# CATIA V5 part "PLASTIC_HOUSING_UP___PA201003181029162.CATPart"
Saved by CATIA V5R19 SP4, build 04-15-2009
Part number: PLASTIC_HOUSING_UP___PA201003181029162
Bounding box of the stored display mesh (mm): x -26 to 26, y -20.64 to 95, z -0.5 to 11
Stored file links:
  E:\CadInnWork\1\PLASTIC_HOUSING_UP___PA201003181029162.CATPart
  C:\Documents and Settings\moren\Bureau\3D models\Lampe\CATIA_V5\pocket_lamp.CATProduct
  C:\Documents and Settings\moren\Bureau\3D models\Lampe\CATIA_V5\switch.CATPart
  C:\Documents and Settings\moren\Bureau\3D models\Lampe\CATIA_V5\led.CATPart
  C:\Documents and Settings\moren\Bureau\3D models\Lampe\CATIA_V5\insert.CATPart
  C:\Documents and Settings\moren\Bureau\3D models\Lampe\CATIA_V5\battery_holder.CATPart
  C:\Documents and Settings\moren\Bureau\3D models\Lampe\CATIA_V5\printed_circuit_board.CATPart
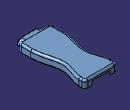
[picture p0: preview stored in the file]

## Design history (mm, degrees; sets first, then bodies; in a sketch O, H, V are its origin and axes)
Parameters
  Update = false
  PDM_version = "A"
  PDM_iteration = 1
  PDM_owner = "moren                    "
  PDM_comment = ""
  PDM_partnumber = "PA002170EA6A57201003181029160002"
Set1
  DatumCurve1: linked copy from another document
  Plane1: linked copy from another document
  DatumCurve2: linked copy from another document
  DatumCurve3: linked copy from another document
  DatumSurface1: linked copy from another document
  Plane2: linked copy from another document
  DatumCurve4: linked copy from another document
  DatumCurve5: linked copy from another document
  DatumSurface2: linked copy from another document
  DatumCurve6: linked copy from another document
  DatumCurve7: linked copy from another document
Body1 (main body)
  Sketch1 on xy-plane, origin (0, 0, 0), H (1, 0, 0), V (0, 1, 0)
    point P1 (0, -10.14)
    line L1 (0, -10.14) -> (-21, -10.14)
    point P2 (-24, -10.14)
    line L2 (0, 93) -> (-21, 93)
    line L3 (-24, 90) -> (-24, 85.2347)
    point P4 (-24, -10.14)
    reference projected line E1 (-14.9, -10.14) -> (-9.5, -10.14) from edge of DatumCurve2
    reference projected circle E2 centre (-20, 89) radius 2.5 from edge of DatumCurve3
    arc A1 centre (-21, 90) radius 3 from (-21, 93) to (-24, 90) ccw
    arc A2 centre (-21, -7.14) radius 3 from (-21, -10.14) to (-24, -7.14) cw
    line L4 (0, 93) -> (0, -10.14)
    spline S1 through (-24, 8.6583) (-20.9977, 71.7619) (-24, 85.2347)
    reference intersected line E3 through (0, 0) direction (0, 1) from Plane2
    line L5 (-24, 8.6583) -> (-24, -7.14)
    point P11 (-24, 85.2347)
    point P12 (-24, 8.6583)
    reference projected line E4 (-13.2, 95) -> (13.2, 95) from DatumCurve1
    point P13 (-24, 8.6583)
    point P14 (-24, 85.2347)
    distance E2 L3 = 1.5
    radius A1 = 3
    radius A2 = 3
    distance S1 E3 = 16.5
    distance L2 E4 = 2
    coincidence: P1 V, P4 P2, L1 E1, L1 P2, L3 P4, P13 L3, P14 L3, P14 P11, P13 P12, L3 L5
    horizontal: L1 H, L2 H
    vertical: L3 V, L4 V, L5 V
    tangency: A1 L2, A1 L3, A2 L1, A2 L3
  Pad1: profile Sketch1, direction (0, 0, 1), up to face of DatumSurface1
  Thickness1: Thickness 1, Face end face of Pad1
  Fillet1: radius 1, on edge [end face of Pad1 | face of Pad1 from Sketch1.S1]
  Shell1: IntOffset 0, Face (start face of Pad1; face of Pad1 from Sketch1.L4), ExtOffset 2
  Sketch2 on end face of Pad1, origin (0, 0, 9), H (1, 0, 0), V (0, -1, 0)
    circle A1 centre (-20, 6.14) radius 4.5
    circle A2 centre (-20, 6.14) radius 2.4
    radius A2 = 2.4
    distance A2 A1 = 2.1
  Pad2: profile Sketch2, direction (0, 0, -1), length 6.5
  Fillet2: radius 0.5, on edge [end face of Pad1 | face of Pad2 from Sketch2.A1]; edge [face of Pad1 from Sketch1.A2 | end face of Pad2]; edge [face of Pad2 from Sketch2.A1 | end face of Pad2]
  Sketch3 on end face of Pad1, origin (0, 0, 9), H (1, 0, 0), V (0, -1, 0)
    circle A1 centre (-20, -89) radius 2.4
    reference projected circle E1 centre (-20, -89) radius 2.5 from edge of DatumCurve3
    circle A2 centre (-20, -89) radius 4.5
    radius A1 = 2.4
    distance A1 A2 = 2.1
    concentricity: A1 E1
  Pad3: profile Sketch3, direction (0, 0, -1), length 6.5
  Fillet3: radius 0.5, on edge [end face of Pad1 | face of Pad3 from Sketch3.A2]; edge [face of Pad1 from Sketch1.A1 | end face of Pad3]; edge [face of Pad3 from Sketch3.A2 | end face of Pad3]
  Sketch4 on end face of Pad1, origin (0, 0, 9), H (1, 0, 0), V (0, -1, 0)
    point P1 (0, 0.2)
    line L1 (0, 0.2) -> (-16, 0.2)
    line L2 (-16, 0.2) -> (-16, -1.2)
    line L3 (-16, -1.2) -> (0, -1.2)
    point P4 (0, -1.2)
    reference projected line E1 (15, -1) -> (-15, -1) from edge of DatumCurve5
    reference intersected line E2 through (0, 0) direction (-1, 0) from face of DatumSurface2
    reference projected line E3 (-15, 0) -> (-15, -1) from edge of DatumCurve6
    line L4 (0, -1.2) -> (0, -2.95)
    line L5 (0, -2.95) -> (-15.8, -2.95)
    line L6 (-17.75, -27.95) -> (-17.75, -0.05)
    line L7 (-15.75, 1.95) -> (0, 1.95)
    point P6 (0, 1.95)
    line L8 (0, 1.95) -> (0, 0.2)
    arc A1 centre (-15.75, -0.05) radius 2 from (-15.75, 1.95) to (-17.75, -0.05) ccw
    point P10 (-17.75, -27.95)
    line L9 (-16, -3.15) -> (-16, -27.95)
    line L10 (-16, -27.95) -> (-17.75, -27.95)
    point P12 (-17.75, -27.95)
    arc A2 centre (-15.8, -3.15) radius 0.2 from (-15.8, -2.95) to (-16, -3.15) ccw
    distance E1 L3 = 0.2
    distance L1 E2 = 0.2
    distance E3 L2 = 1
    distance L1 L7 = 1.75
    distance L2 L6 = 1.75
    distance L5 L3 = 1.75
    radius A1 = 2
    distance L9 L6 = 1.75
    radius A2 = 0.2
    distance L10 L5 = 25
    coincidence: P1 V, P4 V, P6 V, P12 L6, P10 P12
    horizontal: L1 H, L3 H, L5 H, L7 H, L10 H
    vertical: L2 V, L4 V, L6 V, L8 V, L9 V
    tangency: A1 L7, A1 L6, A2 L5, A2 L9
  Pad4: profile Sketch4, direction (0, 0, -1), length 7.5
  Fillet4: radius 0.5, on edge [face of Pad4 from Sketch4.L5 | end face of Pad1]; edge [face of Pad4 from Sketch4.L6 | end face of Pad1]; edge [face of Pad4 from Sketch4.L10 | end face of Pad1]; edge [face of Pad4 from Sketch4.L9 | face of Pad4 from Sketch4.L10]; edge [face of Pad4 from Sketch4.L10 | face of Pad4 from Sketch4.L6]; edge [end face of Pad4 | face of Pad4 from Sketch4.L6]; edge [end face of Pad4 | face of Pad4 from Sketch4.L9]; edge [end face of Pad4 | face of Pad4 from Sketch4.L3]; edge [end face of Pad4 | face of Pad4 from Sketch4.L2]; edge [end face of Pad4 | face of Pad4 from Sketch4.L1]; edge [face of Pad4 from Sketch4.L1 | face of Pad4 from Sketch4.L2]; edge [face of Pad4 from Sketch4.L2 | face of Pad4 from Sketch4.L3]
  Sketch5 on end face of Pad1, origin (0, 0, 9), H (1, 0, 0), V (0, -1, 0)
    point P1 (0, -64)
    line L1 (0, -64) -> (-19.3403, -64)
    line L2 (-19.3403, -64) -> (-20.1053, -65.75)
    line L3 (-20.1053, -65.75) -> (0, -65.75)
    point P4 (0, -65.75)
    line L4 (0, -65.75) -> (0, -64)
    reference projected line E1 (-10, -64) -> (10, -64) from edge of DatumCurve7
    distance L1 L3 = 1.75
    coincidence: P1 V, P4 V, L1 E1
    horizontal: L1 H, L3 H
    vertical: L4 V
  Pad5: profile Sketch5, direction (0, 0, -1), length 7.5
  Fillet5: radius 0.5, on edge [end face of Pad1 | face of Pad5 from Sketch5.L3]; edge [end face of Pad5 | face of Pad1 from Sketch1.S1]; edge [face of Pad5 from Sketch5.L3 | end face of Pad5]; edge [face of Pad5 from Sketch5.L1 | end face of Pad5]
  Sketch6 on face of Shell1, origin (0, 95, 0), H (-1, 0, 0), V (0, 0, 1)
    line L1 (0, 0) -> (15.025, 0)
    line L2 (15.025, 0) -> (15.025, 5.525)
    line L3 (15.025, 5.525) -> (0, 5.525)
    line L4 (0, 5.525) -> (0, 0)
    length L2 = 5.525
    length L3 = 15.025
    horizontal: L1 H, L3 H
    vertical: L2 V, L4 V
  Pocket1: profile Sketch6, direction (0, -1, 0), through (limit type 6)
  Sketch7 on face of Shell1, origin (0, -12.14, 0), H (1, 0, 0), V (0, 0, 1)
    circle A1 centre (-12, 0) radius 2.5
    reference projected arc E1 centre (-12, 0) radius 2.9 from (-9.5, 1.4697) to (-9.5, -1.4697) ccw from edge of DatumCurve2
    radius A1 = 2.5
    concentricity: A1 E1
  Pocket2: profile Sketch7, direction (0, 1, 0), up to face of Pad1 from Sketch1.L1
  RectPattern1: of Pocket2, direction 1 instances 3, spacing 6, along edge [face of Shell1 | start face of Pad1] reversed
  Sketch8 on face of Shell1, origin (0, -12.14, 0), H (1, 0, 0), V (0, 0, 1)
    point P1 (0, 4.9)
    line L1 (0, 4.9) -> (-12, 4.9)
    point P2 (-12, 4.9)
    spline S1 through (-12, 4.9) (-16.9, 0)
    construction line L2 (-12, 4.9) -> (-12, 0)
    point P4 (-12, 4.9)
    point P5 (-16.9, 0)
    coincidence: P1 V, P4 P2, P5 H
    horizontal: L1 H
    vertical: L2 V
  Pad6: profile Sketch8, direction (0, -1, 0), length 7.5, thin wall 0, second thickness 2
  Fillet6: radius 0.5, on edge [face of Shell1 | face of Pad6]; edge [face of Pad6 | face of Shell1]
  Sketch9 on end face of Pad6, origin (0, -19.64, 0), H (1, 0, 0), V (0, 0, 1)
    point P1 (-18.9, 0)
    line L1 (-18.9, 0) -> (-18.9, -0.5)
    line L2 (-18.9, -0.5) -> (-18.025, -0.5)
    line L3 (-18.025, -0.5) -> (-18.025, 0)
    point P4 (-18.025, 0)
    reference projected point E1 (-18.9, 0) from Sketch10.E1
    reference intersected line E2 through (0, 0) direction (-1, 0) from face of Pad6
    line L4 (-18.025, 0) -> (-18.9, 0)
    length L1 = 0.5
    length L2 = 0.875
    vertical: L1 V, L3 V
    horizontal: L2 H, L4 H
    coincidence: P1 E1, P4 E2
  Sketch10 on face of Pad6, origin (0, 0, 0), H (1, 0, 0), V (0, -1, 0)
    projected line E1 (-18.9, 12.64) -> (-18.9, 19.64) from edge [face of Pad6 | face of Pad6]
    projected arc E2 centre (-19.4, 12.64) radius 0.5 from (-19.4, 12.14) to (-18.9, 12.64) ccw from edge [face of Fillet6 | face of Pad6]
    projected line E3 (-19.4, 12.14) -> (-21, 12.14) from edge [face of Shell1 | face of Pad6]
    projected arc E4 centre (-21, 7.14) radius 5 from (-21, 12.14) to (-26, 7.14) ccw from edge [face of Pad6 | face of Shell1]
    projected line E5 (-26, -8.6583) -> (-26, 7.14) from edge [face of Pad6 | face of Shell1]
    projected curve E6 from edge [face of Pad6 | face of Shell1]
    projected line E7 (-26, -90) -> (-26, -85.2347) from edge [face of Pad6 | face of Shell1]
    projected arc E8 centre (-21, -90) radius 5 from (-26, -90) to (-21, -95) ccw from edge [face of Pad6 | face of Shell1]
    projected line E9 (-15.025, -95) -> (-21, -95) from edge [face of Pad6 | face of Shell1]
  Rib1: profile Sketch9, centre curve Sketch10
  Mirror1: of the body so far, about yz-plane
  Sketch11 on face of Pad6, origin (0, 0, 0), H (1, 0, 0), V (0, -1, 0)
    point P1 (-16.9, 19.64)
    line L1 (-16.9, 19.64) -> (-17.9, 19.64)
    line L2 (-17.9, 19.64) -> (-17.9, 18.64)
    line L3 (-17.9, 18.64) -> (-16.9, 18.64)
    line L4 (-16.9, 18.64) -> (-16.9, 19.64)
    reference projected point E1 (-16.9, 19.64) from Sketch12.P6
    length L1 = 1
    length L4 = 1
    horizontal: L1 H, L3 H
    vertical: L2 V, L4 V
    coincidence: P1 E1
  Sketch12 on face of Rib1, origin (0, -19.64, 0), H (1, 0, 0), V (0, 0, 1)
    projected curve E1 from edge [face of Mirror1 | face of Rib1]
    projected line E2 (-12, 4.9) -> (12, 4.9) from edge [face of Pad6 | face of Rib1]
    projected curve E3 from edge [face of Rib1 | face of Pad6]
    point P6 (-16.9, 0)
  Slot1: profile Sketch11, centre curve Sketch12
  Sketch13 on face of Rib1, origin (0, -19.64, 0), H (1, 0, 0), V (0, 0, 1)
    projected curve E1 from edge [face of Rib1 | face of Mirror1]
    projected line E2 (-12, 6.9) -> (12, 6.9) from edge [face of Rib1 | face of Pad6]
    projected curve E3 from edge [face of Pad6 | face of Rib1]
    projected curve E4 from edge [face of Slot1 | face of Mirror1]
    projected line E5 (-12, 4.9) -> (12, 4.9) from edge [face of Pad6 | face of Slot1]
    projected curve E6 from edge [face of Slot1 | face of Pad6]
    line L1 (-18.025, 0) -> (-16.9, 0)
    line L2 (18.9, 0) -> (18.9, -0.5)
    point P13 (18.9, -0.5)
    reference projected point E7 (18.9, -0.5) from vertex [face of Mirror1 | face of Mirror1 | face of Mirror1]
    line L3 (18.9, -0.5) -> (18.025, -0.5)
    line L4 (18.025, -0.5) -> (18.025, 0)
    point P15 (18.025, 0)
    line L5 (18.025, 0) -> (16.9, 0)
    reference projected line E8 (18.025, -0.5) -> (18.025, 0) from edge [face of Mirror1 | face of Mirror1]
    line L6 (-18.9, 0) -> (-18.9, -0.5)
    line L7 (-18.9, -0.5) -> (-18.025, -0.5)
    line L8 (-18.025, -0.5) -> (-18.025, 0)
    reference projected line E9 (-18.9, -0.5) -> (-18.025, -0.5) from edge [face of Rib1 | face of Rib1]
    reference projected line E10 (-18.025, -0.5) -> (-18.025, 0) from edge [face of Rib1 | face of Rib1]
    horizontal: L1 H, L3 H, L5 H, L7 H
    vertical: L2 V, L4 V, L6 V
    coincidence: P13 E7, P15 H, L4 E8, L7 E9, L8 E10
  Pad7: profile Sketch13, direction (0, -1, 0), length 1
  Fillet7: radius 0.5, on edge [face of Pad7 from Sketch13.E1 | end face of Pad7]; edge [face of Pad7 from Sketch13.E4 | end face of Pad7]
